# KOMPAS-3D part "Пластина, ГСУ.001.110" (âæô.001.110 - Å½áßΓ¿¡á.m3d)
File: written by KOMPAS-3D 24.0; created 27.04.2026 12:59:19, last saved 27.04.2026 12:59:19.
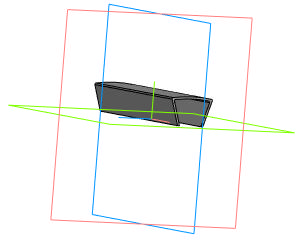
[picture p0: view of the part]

Document properties: Автор: User7; Полное имя файла: C:\Users\User7\Desktop\олимп\ГСУ.001.110 - Пластина.m3d

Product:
- Part/product: Пластина  | designation ГСУ.001.110
    Масса: 0.003574

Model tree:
1. Эскиз:1
2. Элемент выдавливания:1
     Расстояние 1 = 38
3. Скругление:1  (with: Ребро.Элемент выдавливания:1)
     Радиус = 0.3

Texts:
  ГСУ.001.110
